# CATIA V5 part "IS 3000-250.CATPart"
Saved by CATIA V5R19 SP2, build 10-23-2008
Part number: IS 3000-250
Bounding box of the stored display mesh (mm): x -47.487 to 47.487, y -47.487 to 47.487, z 0 to 620
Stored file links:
  C:\Users\Bora\Desktop\3D Katı model\IS serisi\IS 3000\IS 3000-250.CATPart
  C:\Program Files\Dassault Systemes\B19\intel_a\reffiles\standard\MetricThickPitch.txt
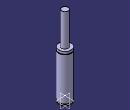
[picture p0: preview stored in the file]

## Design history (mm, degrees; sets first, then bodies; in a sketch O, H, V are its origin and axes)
Body1 (main body)
  Sketch1 on yz-plane, origin (0, 0, 0), H (0, 1, 0), V (0, 0, 1)
    point P1 (47.5, 348.5)
    point P4 (47.5, 343.5)
    point P7 (25, 619)
    point P9 (25, 619)
    point P13 (47.5, 348.5)
    point P14 (47.5, 343.5)
    line L1 (47.5, 348.5) -> (47.5, 367)
    line L2 (47.5, 13) -> (47.5, 343.5)
    line L3 (43.5, 13) -> (43.5, 8)
    arc A1 centre (24, 619) radius 1 from (25, 619) to (24, 620) ccw
    line L4 (25, 619) -> (25, 367)
    line L5 (47.5, 0) -> (47.5, 8)
    arc A2 centre (47.5, 346) radius 2.5 from (47.5, 348.5) to (47.5, 343.5) ccw
    line L6 (24, 620) -> (0, 620)
    point P15 (0, 620)
    line L7 (25, 367) -> (47.5, 367)
    line L8 (0, 0) -> (47.5, 0)
    line L9 (43.5, 13) -> (47.5, 13)
    line L10 (43.5, 8) -> (47.5, 8)
    coincidence: P15 V, P1 P13, P4 P14, P7 P9
    tangency: L6 A1
    horizontal: L7 H, L8 H, L9 H, L10 H
  Shaft1: profile Sketch1, axis Sketch1.V, angle 360
  Sketch2 on face of Shaft1 from Sketch1.L8, origin (0, 0, 0), H (1, 0, 0), V (0, -1, 0)
    point P1 (30, 0)
    distance P1 V = 30
  Hole1: placed by Sketch2, at (30, 0, 0) direction (0, 0, 1), diameter 6.647, depth 13, threaded "M8", thread diameter 8, thread depth 13, pitch 1.25
  CircPattern1: of Hole1, instances 4, angular step 90, axis from xy-plane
